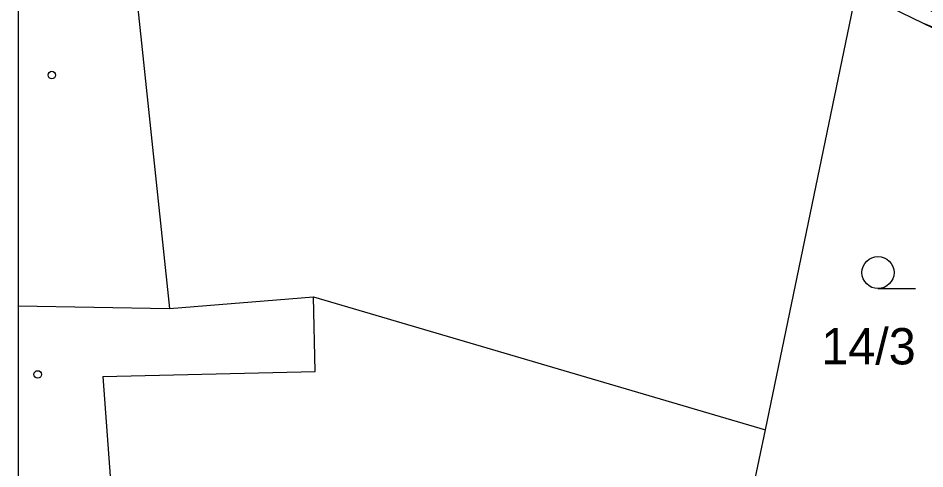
# Model space of a CAD drawing. Extents: x -564037 to -563827, y -1163561 to -1163412.
# Drawn here: x -564036.51 to -563994.02, y -1163483.1 to -1163462 of the extents above; entities that cross this region are included whole.
import ezdxf

# ---------------------------------------------------------------- set-up
doc = ezdxf.new("R2010")
doc.units = 0
for name, color, linetype in [('_rám RT1', 7, 'Continuous'), ('Hranice parcel', 7, 'Continuous'), ('Parcelní čísla', 7, 'Continuous'), ('Vnitřní kresba', 7, 'Continuous'), ('Vrstva 14', 7, 'Continuous'), ('Vrstva 24', 7, 'Continuous'), ('Vrstva 26', 7, 'Continuous'), ('Značky budov', 7, 'Continuous'), ('Značky kultur', 7, 'Continuous')]:
    doc.layers.add(name, color=color, linetype=linetype)

msp = doc.modelspace()

# ---------------------------------------------------------------- linework, layer by layer
at = {"layer": '_rám RT1'}
msp.add_line((-564036.505, -1163412.494), (-564036.505, -1163560.994), dxfattribs=at)
at = {"layer": 'Hranice parcel'}
for p, q in [((-564001.49, -1163481.27), (-563996.99, -1163459.6)), ((-564003.59, -1163491.36), (-564001.49, -1163481.27))]:
    msp.add_line(p, q, dxfattribs=at)
msp.add_lwpolyline([(-564036.505, -1163475.472), (-564029.42, -1163475.59), (-564022.66, -1163475.05), (-564001.49, -1163481.27)], dxfattribs=at)
at = {"layer": 'Vnitřní kresba'}
for p, q in [((-564030.92, -1163461.24), (-564029.42, -1163475.59)), ((-564022.58, -1163478.54), (-564022.66, -1163475.05)), ((-564032.54, -1163478.78), (-564022.58, -1163478.54)), ((-564032.54, -1163478.78), (-564032.18, -1163483.66))]:
    msp.add_line(p, q, dxfattribs=at)
at = {"layer": 'Vrstva 14'}
for points in [[(-564018.41, -1163451.2), (-564015.23, -1163452.19), (-564012.52, -1163453.4), (-564007.28, -1163455.88), (-563999.25, -1163459.72), (-563994.12, -1163462.21), (-563988.58, -1163464.9), (-563990.48, -1163473.96), (-563991.73, -1163479.99), (-563994.29, -1163491.84), (-564004.63, -1163491.62)], [(-563994.12, -1163462.21), (-563988.34, -1163464.58), (-563987.88, -1163465.6), (-563989.98, -1163474.05), (-563991.36, -1163480.01), (-563993.23, -1163488.68), (-563992.87, -1163489.46), (-563993.2, -1163491.27), (-563993.97, -1163492.39), (-563995.48, -1163492.66)]]:
    msp.add_lwpolyline(points, dxfattribs=at)
at = {"layer": 'Vrstva 24'}
msp.add_spline([(-563991.61, -1163470.32), (-563991.26, -1163463.599), (-563991.373, -1163463.232), (-563991.682, -1163462.941), (-563992.084, -1163462.697), (-563992.472, -1163462.472), (-563993.962, -1163461.504), (-563994.869, -1163460.913), (-563995.126, -1163460.722), (-563995.189, -1163460.629), (-563995.21, -1163460.506), (-563995.196, -1163460.381), (-563995.176, -1163460.327), (-563995.163, -1163460.303), (-563995.149, -1163460.283), (-563994.99, -1163460.205), (-563994.767, -1163460.222), (-563994.271, -1163460.322)], degree=3, dxfattribs=at)
at = {"layer": 'Vrstva 26'}
msp.add_spline([(-563981.025, -1163470.232), (-563980.912, -1163469.888), (-563980.721, -1163469.359), (-563980.455, -1163469.109), (-563979.338, -1163468.72), (-563978.809, -1163468.6), (-563977.643, -1163468.592), (-563977.22, -1163468.599), (-563976.885, -1163468.556), (-563976.724, -1163468.485), (-563976.565, -1163468.368), (-563976.376, -1163468.112), (-563976.314, -1163467.841), (-563976.416, -1163467.526), (-563976.542, -1163467.378), (-563976.671, -1163467.251), (-563976.952, -1163467.03), (-563977.65, -1163466.569), (-563978.549, -1163465.84), (-563978.939, -1163465.394), (-563979.079, -1163465.14), (-563979.164, -1163464.863), (-563979.217, -1163464.251), (-563979.201, -1163463.638), (-563979.191, -1163463.509), (-563979.227, -1163463.215), (-563979.312, -1163462.926), (-563979.613, -1163462.412), (-563980.263, -1163461.658), (-563981.187, -1163460.597), (-563982.276, -1163459.401), (-563983.348, -1163458.345), (-563983.91, -1163457.843), (-563984.486, -1163457.355), (-563984.765, -1163457.152), (-563985.705, -1163456.611), (-563986.932, -1163455.859), (-563987.441, -1163455.623), (-563987.975, -1163455.459), (-563988.519, -1163455.337), (-563989.06, -1163455.225), (-563989.608, -1163455.288), (-563990.171, -1163455.536), (-563990.727, -1163455.708), (-563990.996, -1163455.683), (-563991.127, -1163455.629), (-563991.254, -1163455.541), (-563991.448, -1163455.234), (-563991.473, -1163454.874), (-563991.455, -1163454.503), (-563991.469, -1163454.326), (-563991.519, -1163454.162), (-563991.744, -1163453.669), (-563991.977, -1163453.173), (-563992.243, -1163452.692), (-563992.565, -1163452.246), (-563992.58, -1163452.23), (-563992.719, -1163452.103), (-563993.823, -1163451.322), (-563994.944, -1163450.57), (-563997.211, -1163449.107), (-563997.509, -1163448.919), (-563998.192, -1163448.428), (-563998.716, -1163447.621), (-563998.794, -1163447.135), (-563998.844, -1163446.648), (-563998.884, -1163445.672), (-563998.889, -1163444.67), (-563998.889, -1163444.661)], degree=3, dxfattribs=at)
at = {"layer": 'Značky budov'}
for centre in [(-564034.927, -1163464.659), (-564035.587, -1163478.679)]:
    msp.add_circle(centre, 0.175, dxfattribs=at)
at = {"layer": 'Značky kultur'}
msp.add_line((-563996.213, -1163474.66), (-563994.463, -1163474.66), dxfattribs=at)
msp.add_circle((-563996.213, -1163473.91), 0.75, dxfattribs=at)

# ---------------------------------------------------------------- texts
at = {"layer": 'Parcelní čísla'}
msp.add_text('14/3', height=1.7, dxfattribs=at).set_placement((-563998.869, -1163478.21))

doc.saveas('drawing.dxf')
